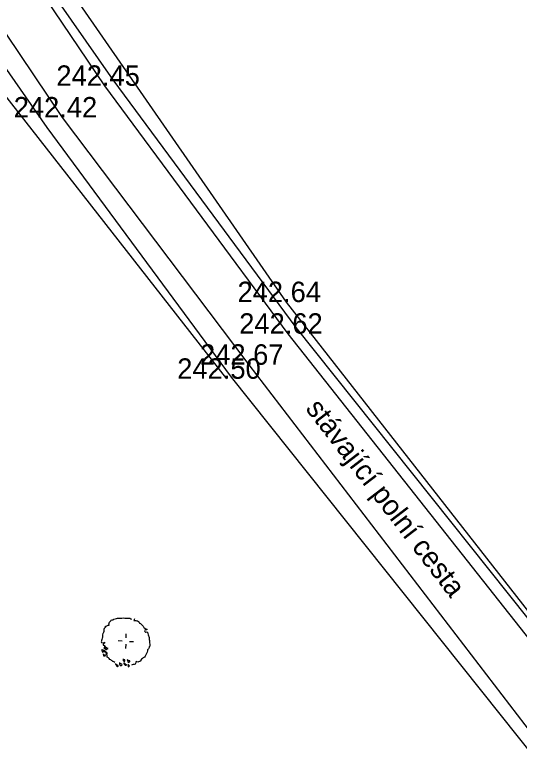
# Model space of a CAD drawing. Extents: x -601589 to -601440, y -1201842 to -1201527.
# Drawn here: x -601490.33 to -601465.62, y -1201701.17 to -1201664.93 of the extents above; entities that cross this region are included whole.
import ezdxf

# ---------------------------------------------------------------- set-up
doc = ezdxf.new("R2010")
doc.units = 0
for name, color, linetype in [('Hranice parcel', 7, 'Continuous'), ('u_hrany', 7, 'Continuous'), ('u_popis', 7, 'Continuous'), ('u_vysadba', 7, 'Continuous'), ('u_vyska', 7, 'Continuous')]:
    doc.layers.add(name, color=color, linetype=linetype)

msp = doc.modelspace()

# ---------------------------------------------------------------- linework, layer by layer
at = {"layer": 'Hranice parcel'}
for points in [[(-601518.5, -1201574.62), (-601510.22, -1201581.07), (-601510.94, -1201612.53), (-601510.72, -1201619.53), (-601510.05, -1201624.75), (-601508.24, -1201633.75), (-601505.86, -1201640.82), (-601502.47, -1201648.58), (-601498.5, -1201656.04), (-601493.62, -1201663.46), (-601488.75, -1201670.45), (-601479.72, -1201682.69), (-601461.88, -1201705.09), (-601445.87, -1201723.83)], [(-601460.43, -1201700.48), (-601476.54, -1201680.26), (-601485.5, -1201668.12), (-601490.31, -1201661.22), (-601495.06, -1201653.99), (-601498.9, -1201646.76), (-601502.13, -1201639.37), (-601504.35, -1201632.81), (-601505.66, -1201626.3)]]:
    msp.add_lwpolyline(points, dxfattribs=at)
at = {"layer": 'u_hrany'}
for points in [[(-601460.33, -1201700.35), (-601477.02, -1201679.01), (-601490.59, -1201659.41), (-601493.47, -1201654.35), (-601500.4, -1201641.28), (-601502.56, -1201635.52), (-601504.77, -1201626.02), (-601500.77, -1201618.77)], [(-601443.32, -1201721.42), (-601460.41, -1201701.5), (-601476.94, -1201680.56), (-601485.91, -1201668.41), (-601495.49, -1201654.25), (-601502.92, -1201639.69), (-601504.84, -1201632.93)], [(-601507.17, -1201633.88), (-601501.63, -1201648), (-601497.69, -1201655.55), (-601488, -1201669.96), (-601478.86, -1201682.08), (-601462.72, -1201703.16), (-601444.89, -1201723.91)], [(-601502.92, -1201648.81), (-601499.15, -1201656.12), (-601494.42, -1201664.28), (-601479.96, -1201682.77)]]:
    msp.add_lwpolyline(points, dxfattribs=at)
at = {"layer": 'u_vysadba'}
for points in [[(-601485.877, -1201694.932), (-601485.876, -1201694.903), (-601485.816, -1201694.877), (-601485.786, -1201694.864), (-601485.756, -1201694.85), (-601485.727, -1201694.852), (-601485.698, -1201694.854), (-601485.711, -1201694.824), (-601485.724, -1201694.794), (-601485.707, -1201694.751), (-601485.69, -1201694.708), (-601485.658, -1201694.665), (-601485.628, -1201694.638), (-601485.597, -1201694.61), (-601485.552, -1201694.583), (-601485.508, -1201694.585), (-601485.477, -1201694.558), (-601485.402, -1201694.532), (-601485.343, -1201694.521), (-601485.299, -1201694.509), (-601485.24, -1201694.512), (-601485.196, -1201694.499), (-601485.152, -1201694.502), (-601485.079, -1201694.506), (-601485.005, -1201694.495), (-601484.932, -1201694.499), (-601484.844, -1201694.503), (-601484.757, -1201694.508), (-601484.684, -1201694.512), (-601484.641, -1201694.529), (-601484.612, -1201694.545)], [(-601484.466, -1201694.538), (-601484.482, -1201694.566), (-601484.483, -1201694.596), (-601484.499, -1201694.624), (-601484.455, -1201694.612), (-601484.426, -1201694.613), (-601484.396, -1201694.615), (-601484.353, -1201694.632), (-601484.31, -1201694.634), (-601484.267, -1201694.666), (-601484.24, -1201694.696), (-601484.213, -1201694.742), (-601484.171, -1201694.773), (-601484.114, -1201694.82), (-601484.073, -1201694.866), (-601484.045, -1201694.897), (-601484.005, -1201694.958), (-601483.948, -1201694.99), (-601483.905, -1201695.021), (-601483.862, -1201695.038), (-601483.864, -1201695.068)], [(-601485.877, -1201694.932), (-601485.878, -1201694.947), (-601485.924, -1201694.988), (-601485.955, -1201695.016), (-601485.957, -1201695.059), (-601485.96, -1201695.103), (-601485.963, -1201695.162), (-601485.98, -1201695.205), (-601485.996, -1201695.233), (-601486.012, -1201695.262), (-601486.03, -1201695.319), (-601486.031, -1201695.348), (-601486.034, -1201695.407), (-601486.037, -1201695.451), (-601486.038, -1201695.48), (-601486.057, -1201695.552), (-601486.074, -1201695.595), (-601486.076, -1201695.639), (-601486.092, -1201695.667), (-601486.079, -1201695.697), (-601486.036, -1201695.714), (-601485.947, -1201695.69), (-601485.917, -1201695.677), (-601485.949, -1201695.733), (-601485.98, -1201695.761), (-601485.996, -1201695.79), (-601485.998, -1201695.833), (-601485.969, -1201695.835), (-601485.925, -1201695.837), (-601485.912, -1201695.867), (-601485.929, -1201695.91), (-601485.945, -1201695.939), (-601485.948, -1201695.982), (-601485.95, -1201696.026)], [(-601484.878, -1201695.473), (-601484.867, -1201695.269)], [(-601483.864, -1201695.068), (-601483.909, -1201695.08), (-601483.953, -1201695.092), (-601483.969, -1201695.121), (-601483.956, -1201695.151), (-601483.929, -1201695.196), (-601483.899, -1201695.183), (-601483.855, -1201695.171), (-601483.827, -1201695.201), (-601483.814, -1201695.231), (-601483.816, -1201695.26), (-601483.789, -1201695.32), (-601483.777, -1201695.365), (-601483.765, -1201695.41), (-601483.738, -1201695.455), (-601483.74, -1201695.484), (-601483.742, -1201695.528), (-601483.743, -1201695.557), (-601483.731, -1201695.602), (-601483.72, -1201695.661), (-601483.723, -1201695.719), (-601483.711, -1201695.778), (-601483.713, -1201695.808), (-601483.714, -1201695.837), (-601483.717, -1201695.881), (-601483.747, -1201695.908), (-601483.749, -1201695.938), (-601483.766, -1201695.981), (-601483.782, -1201696.009), (-601483.828, -1201696.051), (-601483.831, -1201696.109), (-601483.849, -1201696.167), (-601483.867, -1201696.239), (-601483.914, -1201696.295), (-601483.947, -1201696.366), (-601483.979, -1201696.423), (-601484.039, -1201696.449), (-601484.07, -1201696.477), (-601484.116, -1201696.519), (-601484.148, -1201696.561), (-601484.165, -1201696.604), (-601484.225, -1201696.63), (-601484.269, -1201696.642), (-601484.299, -1201696.655), (-601484.342, -1201696.638), (-601484.385, -1201696.621), (-601484.402, -1201696.664), (-601484.42, -1201696.722), (-601484.437, -1201696.765), (-601484.481, -1201696.777), (-601484.525, -1201696.775)], [(-601485.062, -1201695.625), (-601485.266, -1201695.614)], [(-601484.711, -1201695.643), (-601484.506, -1201695.64)], [(-601486.081, -1201696.019), (-601486.068, -1201696.049), (-601486.056, -1201696.094), (-601486.043, -1201696.124), (-601486.044, -1201696.153), (-601486.016, -1201696.169), (-601485.985, -1201696.142), (-601485.939, -1201696.1), (-601485.968, -1201696.099), (-601486.011, -1201696.067), (-601486.054, -1201696.05)], [(-601485.924, -1201696.086), (-601485.882, -1201696.132), (-601485.841, -1201696.178), (-601485.799, -1201696.21)], [(-601485.799, -1201696.21), (-601485.828, -1201696.208), (-601485.857, -1201696.207), (-601485.886, -1201696.205), (-601485.899, -1201696.175), (-601485.898, -1201696.146), (-601485.911, -1201696.116)], [(-601485.899, -1201695.897), (-601485.901, -1201695.941), (-601485.888, -1201695.971), (-601485.876, -1201696.016), (-601485.863, -1201696.046), (-601485.834, -1201696.047), (-601485.818, -1201696.019), (-601485.758, -1201695.993), (-601485.801, -1201695.976), (-601485.829, -1201695.959), (-601485.886, -1201695.927)], [(-601484.894, -1201695.78), (-601484.905, -1201695.985)], [(-601485.991, -1201696.258), (-601485.981, -1201696.347), (-601485.938, -1201696.349), (-601485.908, -1201696.351), (-601485.864, -1201696.338), (-601485.922, -1201696.321), (-601485.965, -1201696.318), (-601485.978, -1201696.288)], [(-601485.427, -1201696.669), (-601485.47, -1201696.652), (-601485.499, -1201696.636), (-601485.528, -1201696.634), (-601485.555, -1201696.589), (-601485.583, -1201696.573), (-601485.626, -1201696.541), (-601485.669, -1201696.524), (-601485.71, -1201696.478), (-601485.738, -1201696.447), (-601485.809, -1201696.414), (-601485.807, -1201696.371), (-601485.805, -1201696.327), (-601485.818, -1201696.297), (-601485.846, -1201696.281), (-601485.815, -1201696.238), (-601485.785, -1201696.24)], [(-601485.416, -1201696.728), (-601485.32, -1201696.85), (-601485.293, -1201696.896), (-601485.261, -1201696.853), (-601485.26, -1201696.824), (-601485.288, -1201696.808), (-601485.331, -1201696.791), (-601485.36, -1201696.775), (-601485.388, -1201696.759)], [(-601485.194, -1201696.681), (-601485.198, -1201696.754), (-601485.185, -1201696.799), (-601485.158, -1201696.83), (-601485.099, -1201696.818), (-601485.068, -1201696.79), (-601485.081, -1201696.76), (-601485.124, -1201696.743), (-601485.167, -1201696.727)], [(-601485.023, -1201696.5), (-601485.012, -1201696.574), (-601484.986, -1201696.619), (-601484.941, -1201696.607), (-601484.939, -1201696.578), (-601484.938, -1201696.548), (-601484.981, -1201696.531), (-601485.009, -1201696.515)], [(-601484.989, -1201696.677), (-601484.905, -1201696.755), (-601484.876, -1201696.771), (-601484.863, -1201696.801), (-601484.894, -1201696.829), (-601484.923, -1201696.827), (-601484.936, -1201696.797), (-601484.963, -1201696.752), (-601484.991, -1201696.721)], [(-601484.82, -1201696.54), (-601484.794, -1201696.6), (-601484.782, -1201696.644), (-601484.754, -1201696.675), (-601484.724, -1201696.662), (-601484.693, -1201696.62), (-601484.691, -1201696.591), (-601484.735, -1201696.588), (-601484.763, -1201696.572), (-601484.792, -1201696.556), (-601484.821, -1201696.554)], [(-601484.79, -1201696.79), (-601484.779, -1201696.864), (-601484.766, -1201696.894), (-601484.736, -1201696.881), (-601484.704, -1201696.839), (-601484.732, -1201696.808), (-601484.76, -1201696.792), (-601484.79, -1201696.79)], [(-601484.525, -1201696.775), (-601484.57, -1201696.787), (-601484.601, -1201696.815)]]:
    msp.add_lwpolyline(points, dxfattribs=at)

# ---------------------------------------------------------------- texts
at = {"layer": 'u_popis'}
msp.add_text('stávající polní cesta ', height=1, rotation=307.4888, dxfattribs=at).set_placement((-601476.117, -1201684.241))
at = {"layer": 'u_vyska'}
for s, p in [('242.45', (-601488.288, -1201668.41)), ('242.42', (-601490.378, -1201669.96)), ('242.64', (-601479.417, -1201679.01)), ('242.62', (-601479.333, -1201680.56)), ('242.67', (-601481.253, -1201682.08)), ('242.50', (-601482.369, -1201682.77))]:
    msp.add_text(s, height=1, dxfattribs=at).set_placement(p)

doc.saveas('drawing.dxf')
